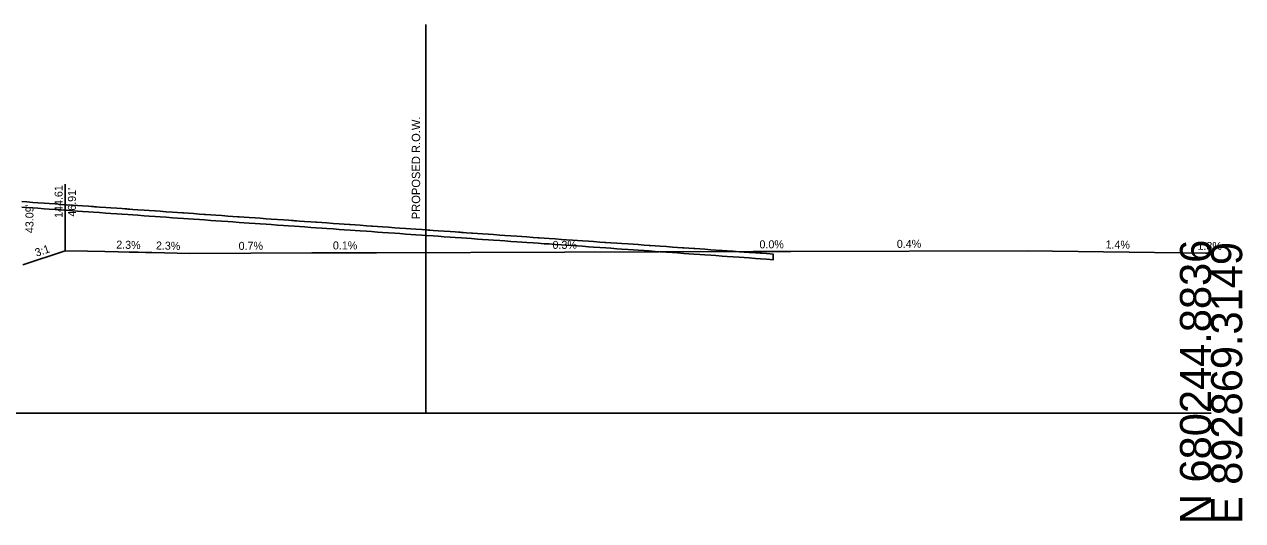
# Model space of a CAD drawing. Extents: x -26 to 4403, y -13 to 9578.
# Drawn here: x 293.2 to 402.8, y 3490.3 to 3535 of the extents above; entities that cross this region are included whole.
import ezdxf

# ---------------------------------------------------------------- set-up
doc = ezdxf.new("R2010")
doc.units = 0
for name, color, linetype in [('CONST_LV3', 7, 'Continuous'), ('DTM_CORRIDOR', 7, 'Continuous'), ('DTM_P_FINISHED_GRADE', 7, 'Continuous'), ('DTM_X_GROUND', 7, 'Continuous'), ('ROW_LINES', 7, 'Continuous'), ('XS_CELL', 7, 'Continuous'), ('XS_P_DR_GRAVEL', 7, 'Continuous'), ('XS_P_GROUND', 7, 'Continuous'), ('XS_P_TX_CLEARZONE', 7, 'Continuous'), ('XS_P_TX_FS_BS', 7, 'Continuous')]:
    doc.layers.add(name, color=color, linetype=linetype)

msp = doc.modelspace()

# ---------------------------------------------------------------- linework, layer by layer
at = {"layer": 'CONST_LV3'}
msp.add_lwpolyline([(293, 3519.04), (293.45, 3519.01), (294, 3518.97), (294.45, 3518.94), (295, 3518.9), (295.45, 3518.87), (296, 3518.83), (296.55, 3518.79), (297, 3518.76), (297.45, 3518.73), (298, 3518.69), (298.45, 3518.66), (299, 3518.62), (299.55, 3518.58), (300, 3518.55), (300.55, 3518.51), (301, 3518.48), (301.55, 3518.44), (302, 3518.41), (302.45, 3518.38), (303, 3518.34), (303.45, 3518.31), (304, 3518.27), (304.45, 3518.24), (305, 3518.2), (305.45, 3518.17), (306, 3518.13), (306.55, 3518.09), (307, 3518.06), (307.45, 3518.03), (308, 3517.99), (308.45, 3517.96), (309, 3517.92), (309.55, 3517.88), (310, 3517.85), (310.45, 3517.82), (311, 3517.78), (311.55, 3517.74), (312, 3517.71), (312.45, 3517.68), (313, 3517.64), (313.45, 3517.61), (314, 3517.57), (314.45, 3517.54), (315, 3517.5), (315.45, 3517.47), (316, 3517.43), (316.55, 3517.39), (317, 3517.36), (317.45, 3517.33), (318, 3517.29), (318.45, 3517.26), (319, 3517.22), (319.55, 3517.18), (320, 3517.15), (320.45, 3517.12), (321, 3517.08), (321.55, 3517.04), (322, 3517.01), (322.45, 3516.98), (323, 3516.94), (323.45, 3516.91), (324, 3516.87), (324.55, 3516.83), (325, 3516.8), (325.45, 3516.77), (326, 3516.73), (326.55, 3516.69), (327, 3516.66), (327.55, 3516.62), (328, 3516.59), (328.45, 3516.56), (329, 3516.52), (329.55, 3516.48), (330, 3516.45), (330.45, 3516.42), (331, 3516.38), (331.55, 3516.34), (332, 3516.31), (332.45, 3516.28), (333, 3516.24), (333.55, 3516.2), (334, 3516.17), (334.45, 3516.14), (335, 3516.1), (335.45, 3516.07), (336, 3516.03), (336.45, 3516), (337, 3515.96), (337.55, 3515.92), (338, 3515.89), (338.45, 3515.86), (339, 3515.82), (339.55, 3515.78), (340, 3515.75), (340.45, 3515.72), (341, 3515.68), (341.55, 3515.64), (342, 3515.61), (342.55, 3515.57), (343, 3515.54), (343.45, 3515.51), (344, 3515.47), (344.45, 3515.44), (345, 3515.4), (345.45, 3515.37), (346, 3515.33), (346.55, 3515.29), (347, 3515.26), (347.55, 3515.22), (348, 3515.19), (348.45, 3515.16), (349, 3515.12), (349.55, 3515.08), (350, 3515.05), (350.45, 3515.02), (351, 3514.98), (351.55, 3514.94), (352, 3514.91), (352.45, 3514.88), (353, 3514.84), (353.55, 3514.8), (354, 3514.77), (354.45, 3514.74), (355, 3514.7), (355.45, 3514.67), (356, 3514.63), (356.45, 3514.6), (357, 3514.56), (357.55, 3514.52), (358, 3514.49), (358.45, 3514.46), (359, 3514.42), (359.55, 3514.38), (360, 3514.35), (360.34, 3514.32), (360.61, 3514.3)], dxfattribs=at)
at = {"layer": 'DTM_P_FINISHED_GRADE'}
msp.add_lwpolyline([(293, 3519.04), (293.45, 3519.01), (294, 3518.97), (294.45, 3518.94), (295, 3518.9), (295.45, 3518.87), (296, 3518.83), (296.55, 3518.79), (297, 3518.76), (297.55, 3518.72), (298, 3518.69), (298.45, 3518.66), (299, 3518.62), (299.45, 3518.59), (300, 3518.55), (300.55, 3518.51), (301, 3518.48), (301.55, 3518.44), (302, 3518.41), (302.55, 3518.37), (303, 3518.34), (303.45, 3518.31), (304, 3518.27), (304.45, 3518.24), (305, 3518.2), (305.45, 3518.17), (306, 3518.13), (306.55, 3518.09), (307, 3518.06), (307.55, 3518.02), (308, 3517.99), (308.45, 3517.96), (309, 3517.92), (309.45, 3517.89), (310, 3517.85), (310.45, 3517.82), (311, 3517.78), (311.55, 3517.74), (312, 3517.71), (312.55, 3517.67), (313, 3517.64), (313.45, 3517.61), (314, 3517.57), (314.45, 3517.54), (315, 3517.5), (315.45, 3517.47), (316, 3517.43), (316.55, 3517.39), (317, 3517.36), (317.55, 3517.32), (318, 3517.29), (318.45, 3517.26), (319, 3517.22), (319.45, 3517.19), (320, 3517.15), (320.45, 3517.12), (321, 3517.08), (321.55, 3517.04), (322, 3517.01), (322.55, 3516.97), (323, 3516.94), (323.45, 3516.91), (324, 3516.87), (324.45, 3516.84), (325, 3516.8), (325.45, 3516.77), (326, 3516.73), (326.55, 3516.69), (327, 3516.66), (327.55, 3516.62), (328, 3516.59), (328.45, 3516.56), (329, 3516.52), (329.45, 3516.49), (330, 3516.45), (330.45, 3516.42), (331, 3516.38), (331.55, 3516.34), (332, 3516.31), (332.55, 3516.27), (333, 3516.24), (333.45, 3516.21), (334, 3516.17), (334.45, 3516.14), (335, 3516.1), (335.45, 3516.07), (336, 3516.03), (336.45, 3516), (337, 3515.96), (337.55, 3515.92), (338, 3515.89), (338.45, 3515.86), (339, 3515.82), (339.45, 3515.79), (340, 3515.75), (340.45, 3515.72), (341, 3515.68), (341.55, 3515.64), (342, 3515.61), (342.55, 3515.57), (343, 3515.54), (343.45, 3515.51), (344, 3515.47), (344.45, 3515.44), (345, 3515.4), (345.55, 3515.36), (346, 3515.33), (346.55, 3515.29), (347, 3515.26), (347.55, 3515.22), (348, 3515.19), (348.45, 3515.16), (349, 3515.12), (349.45, 3515.09), (350, 3515.05), (350.45, 3515.02), (351, 3514.98), (351.55, 3514.94), (352, 3514.91), (352.55, 3514.87), (353, 3514.84), (353.45, 3514.81), (354, 3514.77), (354.45, 3514.74), (355, 3514.7), (355.45, 3514.67), (356, 3514.63), (356.45, 3514.6), (357, 3514.56), (357.55, 3514.52), (358, 3514.49), (358.45, 3514.46), (359, 3514.42), (359.45, 3514.39), (360, 3514.35), (360.34, 3514.32), (360.61, 3514.3)], dxfattribs=at)
at = {"layer": 'DTM_X_GROUND'}
msp.add_lwpolyline([(296.91, 3514.61), (298.91, 3514.57), (300.46, 3514.53), (301.67, 3514.51), (302.65, 3514.48), (303.45, 3514.47), (303.46, 3514.47), (304.12, 3514.45), (304.7, 3514.44), (308.12, 3514.36), (319.1, 3514.43), (324.91, 3514.43), (358.79, 3514.53), (362.2, 3514.53), (383.45, 3514.61), (399.49, 3514.39), (400, 3514.39)], dxfattribs=at)
at = {"layer": 'ROW_LINES'}
msp.add_line((329.35, 3500), (329.35, 3535), dxfattribs=at)
at = {"layer": 'XS_CELL'}
msp.add_line((250, 3500), (400, 3500), dxfattribs=at)
at = {"layer": 'XS_P_DR_GRAVEL'}
msp.add_lwpolyline([(293, 3519.04), (293.45, 3519.01), (294, 3518.97), (294.45, 3518.94), (295, 3518.9), (295.45, 3518.87), (296, 3518.83), (296.55, 3518.79), (297, 3518.76), (297.55, 3518.72), (298, 3518.69), (298.45, 3518.66), (299, 3518.62), (299.45, 3518.59), (300, 3518.55), (300.55, 3518.51), (301, 3518.48), (301.55, 3518.44), (302, 3518.41), (302.55, 3518.37), (303, 3518.34), (303.45, 3518.31), (304, 3518.27), (304.45, 3518.24), (305, 3518.2), (305.45, 3518.17), (306, 3518.13), (306.55, 3518.09), (307, 3518.06), (307.55, 3518.02), (308, 3517.99), (308.45, 3517.96), (309, 3517.92), (309.45, 3517.89), (310, 3517.85), (310.45, 3517.82), (311, 3517.78), (311.55, 3517.74), (312, 3517.71), (312.55, 3517.67), (313, 3517.64), (313.45, 3517.61), (314, 3517.57), (314.45, 3517.54), (315, 3517.5), (315.45, 3517.47), (316, 3517.43), (316.55, 3517.39), (317, 3517.36), (317.55, 3517.32), (318, 3517.29), (318.45, 3517.26), (319, 3517.22), (319.45, 3517.19), (320, 3517.15), (320.45, 3517.12), (321, 3517.08), (321.55, 3517.04), (322, 3517.01), (322.55, 3516.97), (323, 3516.94), (323.45, 3516.91), (324, 3516.87), (324.45, 3516.84), (325, 3516.8), (325.45, 3516.77), (326, 3516.73), (326.55, 3516.69), (327, 3516.66), (327.55, 3516.62), (328, 3516.59), (328.45, 3516.56), (329, 3516.52), (329.45, 3516.49), (330, 3516.45), (330.45, 3516.42), (331, 3516.38), (331.55, 3516.34), (332, 3516.31), (332.55, 3516.27), (333, 3516.24), (333.45, 3516.21), (334, 3516.17), (334.45, 3516.14), (335, 3516.1), (335.45, 3516.07), (336, 3516.03), (336.45, 3516), (337, 3515.96), (337.55, 3515.92), (338, 3515.89), (338.45, 3515.86), (339, 3515.82), (339.45, 3515.79), (340, 3515.75), (340.45, 3515.72), (341, 3515.68), (341.55, 3515.64), (342, 3515.61), (342.55, 3515.57), (343, 3515.54), (343.45, 3515.51), (344, 3515.47), (344.45, 3515.44), (345, 3515.4), (345.55, 3515.36), (346, 3515.33), (346.55, 3515.29), (347, 3515.26), (347.55, 3515.22), (348, 3515.19), (348.45, 3515.16), (349, 3515.12), (349.45, 3515.09), (350, 3515.05), (350.45, 3515.02), (351, 3514.98), (351.55, 3514.94), (352, 3514.91), (352.55, 3514.87), (353, 3514.84), (353.45, 3514.81), (354, 3514.77), (354.45, 3514.74), (355, 3514.7), (355.45, 3514.67), (356, 3514.63), (356.45, 3514.6), (357, 3514.56), (357.55, 3514.52), (358, 3514.49), (358.45, 3514.46), (359, 3514.42), (359.45, 3514.39), (360, 3514.35), (360.34, 3514.32), (360.61, 3514.3), (360.61, 3513.8), (360.34, 3513.82), (360, 3513.85), (359.45, 3513.89), (359, 3513.92), (358.45, 3513.96), (358, 3513.99), (357.55, 3514.02), (357, 3514.06), (356.45, 3514.1), (356, 3514.13), (355.45, 3514.17), (355, 3514.2), (354.45, 3514.24), (354, 3514.27), (353.45, 3514.31), (353, 3514.34), (352.55, 3514.37), (352, 3514.41), (351.55, 3514.44), (351, 3514.48), (350.45, 3514.52), (350, 3514.55), (349.45, 3514.59), (349, 3514.62), (348.45, 3514.66), (348, 3514.69), (347.55, 3514.72), (347, 3514.76), (346.55, 3514.79), (346, 3514.83), (345.55, 3514.86), (345, 3514.9), (344.45, 3514.94), (344, 3514.97), (343.45, 3515.01), (343, 3515.04), (342.55, 3515.07), (342, 3515.11), (341.55, 3515.14), (341, 3515.18), (340.45, 3515.22), (340, 3515.25), (339.45, 3515.29), (339, 3515.32), (338.45, 3515.36), (338, 3515.39), (337.55, 3515.42), (337, 3515.46), (336.45, 3515.5), (336, 3515.53), (335.45, 3515.57), (335, 3515.6), (334.45, 3515.64), (334, 3515.67), (333.45, 3515.71), (333, 3515.74), (332.55, 3515.77), (332, 3515.81), (331.55, 3515.84), (331, 3515.88), (330.45, 3515.92), (330, 3515.95), (329.45, 3515.99), (329, 3516.02), (328.45, 3516.06), (328, 3516.09), (327.55, 3516.12), (327, 3516.16), (326.55, 3516.19), (326, 3516.23), (325.45, 3516.27), (325, 3516.3), (324.45, 3516.34), (324, 3516.37), (323.45, 3516.41), (323, 3516.44), (322.55, 3516.47), (322, 3516.51), (321.55, 3516.54), (321, 3516.58), (320.45, 3516.62), (320, 3516.65), (319.45, 3516.69), (319, 3516.72), (318.45, 3516.76), (318, 3516.79), (317.55, 3516.82), (317, 3516.86), (316.55, 3516.89), (316, 3516.93), (315.45, 3516.97), (315, 3517), (314.45, 3517.04), (314, 3517.07), (313.45, 3517.11), (313, 3517.14), (312.55, 3517.17), (312, 3517.21), (311.55, 3517.24), (311, 3517.28), (310.45, 3517.32), (310, 3517.35), (309.45, 3517.39), (309, 3517.42), (308.45, 3517.46), (308, 3517.49), (307.55, 3517.52), (307, 3517.56), (306.55, 3517.59), (306, 3517.63), (305.45, 3517.67), (305, 3517.7), (304.45, 3517.74), (304, 3517.77), (303.45, 3517.81), (303, 3517.84), (302.55, 3517.87), (302, 3517.91), (301.55, 3517.94), (301, 3517.98), (300.55, 3518.01), (300, 3518.05), (299.45, 3518.09), (299, 3518.12), (298.45, 3518.16), (298, 3518.19), (297.55, 3518.22), (297, 3518.26), (296.55, 3518.29), (296, 3518.33), (295.45, 3518.37), (295, 3518.4), (294.45, 3518.44), (294, 3518.47), (293.45, 3518.51), (293, 3518.54)], dxfattribs=at)
at = {"layer": 'XS_P_GROUND'}
msp.add_lwpolyline([(293.09, 3513.34), (296.91, 3514.61)], dxfattribs=at)
at = {"layer": 'XS_P_TX_CLEARZONE'}
msp.add_line((296.91, 3514.61), (296.91, 3520.61), dxfattribs=at)

# ---------------------------------------------------------------- texts
at = {"layer": 'DTM_CORRIDOR'}
msp.add_text('X', height=0.12, dxfattribs=at).set_placement((296.87, 3514.55))
at = {"layer": 'ROW_LINES'}
msp.add_text('PROPOSED R.O.W.', height=0.75, rotation=90, dxfattribs=at).set_placement((328.84, 3517.45))
at = {"layer": 'XS_CELL'}
for s, p in [('N 680244.8836', (400, 3490)), ('E 892869.3149', (402.8, 3490))]:
    msp.add_text(s, height=2.8, rotation=90, dxfattribs=at).set_placement(p)
at = {"layer": 'XS_P_TX_CLEARZONE'}
for s, p in [('144.61', (296.67, 3517.57)), ("46.91'", (297.87, 3517.68)), ("43.09'", (294.05, 3516.2))]:
    msp.add_text(s, height=0.72, rotation=90, dxfattribs=at).set_placement(p)
at = {"layer": 'XS_P_TX_FS_BS'}
for s, rotation, p in [('2.3%', 358.6995, (301.49, 3514.81)), ('2.3%', 358.6995, (301.49, 3514.81)), ('2.3%', 358.6995, (305.06, 3514.73)), ('2.3%', 358.6995, (305.06, 3514.73)), ('0.7%', 0.3834, (312.51, 3514.69)), ('0.7%', 0.3834, (312.51, 3514.69)), ('0.1%', 359.9588, (320.99, 3514.73)), ('0.1%', 359.9588, (320.99, 3514.73)), ('0.3%', 0.1665, (340.75, 3514.78)), ('0.3%', 0.1665, (340.75, 3514.78)), ('0.0%', 359.9818, (359.37, 3514.83)), ('0.0%', 359.9818, (359.37, 3514.83)), ('0.4%', 0.2373, (371.73, 3514.87)), ('0.4%', 0.2373, (371.73, 3514.87)), ('1.4%', 359.204, (390.5, 3514.82)), ('1.4%', 359.204, (390.5, 3514.82)), ('1.3%', 359.2298, (398.77, 3514.7)), ('1.3%', 359.2298, (398.77, 3514.7)), ('3:1', 18.4349, (294.32, 3514.07))]:
    msp.add_text(s, height=0.72, rotation=rotation, dxfattribs=at).set_placement(p)

doc.saveas('drawing.dxf')
